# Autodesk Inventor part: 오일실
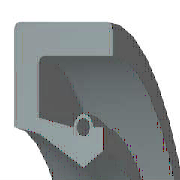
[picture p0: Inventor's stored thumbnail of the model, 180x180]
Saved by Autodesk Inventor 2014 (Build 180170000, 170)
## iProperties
IsCustomPart: 0
Created: 2009-02
Part Number: 오일실
Material: 고무
Description: 오일-실
Document SubType Name: Modeling
Standard: KS B 2804
Designer: 한국산업디자인학원 [http://gmhk.co.kr]
Standards Organization: KS
Language: ko-KR
Size Designation: S - 17 30 8
Categories: <MemberInstance><Categories><Category DisplayName="샤프트 부품" InternalName="7f7aeb1f-a693-4053-b835-cee3144e0d98" Mnemonic="SHFT"><Category DisplayName="실링" Intern
Density: 0.93 g/cm^3
Appearance: 고무 - 검은색 - 버전 1.1
Mass: 1.6913 g
Surface Area: 28.0102 cm^2
Volume: 1.81861 cm^3
Author: pww
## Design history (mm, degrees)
revolve "본체" stored, may be unused: angle "d17" = 90 deg
revolve "스프링1" stored, may be unused: angle "d18" = 90 deg
body "Solid1"
sketch "스케치1"
  geometry: L1 (0, 15)-(8, 15); L2 (8, 15)-(8, 13.75); L3 (8, 13.75)-(1.75, 13.75); L4 (0, 15)-(0, 10.6); L5 (0, 10.6)-(1.75, 10.25); L6 (1.75, 10.25)-(4.9, 8.5); L7 (4.9, 8.5)-(0, 8.5); L8 (6.3, 9.375)-(6.3, 10.6); L9 (0, 0)-(9.586, 0) reference; L10 (4.9, 8.5)-(6.3, 9.375); L11 (0, 18)-(0, -3) reference; L12 (-1.917, 0)-(11.503, 0) reference; L13 (4.2, 10.6)-(1.75, 11.09); L14 (1.75, 11.09)-(1.75, 13.75); L15 (6.3, 10.6)-(5.6, 10.6); C1 r 0.455 at (4.9, 10.6); A1 r 0.7 centre (4.9, 10.6) between (5.6, 10.6) and (4.2, 10.6)
  constraints: 26 end point, 5 horizontal alignment, 4 perpendicular, 2 centre point, 2 collinear, 2 horizontal, 2 parallel, 2 point on circle, 2 point on line, 2 vertical alignment, 1 coincident
  dimensions: "d0" = 30 diameter of L1 L9 (= SD2); "d1" = 18.75 diameter of L8.start L9 (= ABDM); "d2" = 1.25 distance of L1.end L2.end (computed from SD); "d3" = 0.91 diameter of C1 (= SPDI); "d4" = 1.4 diameter of A1 (= SPDA); "d5" = 17 diameter of L6.end L9 (= NND); "d6" = 20.5 diameter of L5.end L9 (= TKDM); "d7" = 21.2 diameter of L4.end L9 (= HLDM); "d8" = 4.9 distance from line of C1.centre L4 (= SPDST); "d9" = 6.3 distance between parallel lines of L8 L4 (= SDI); "d10" = 8 distance between parallel lines of L2 L4 (= SWDT); "d12" = 1.75 distance between parallel lines of L14 L4 (= SD)
fillet "모깎기1" dims "d11" = 0.3 (= RR)
other parameters: "SD2" = 30 [user parameter; used in 1 equation term], "SWDT" = 8 [user parameter; used in 1 equation term], "RR" = 0.3 [user parameter; used in 1 equation term], "SD" = 1.75 [user parameter; used in 2 equation terms], "NND" = 17 [user parameter; used in 1 equation term], "SPDA" = 1.4 [user parameter; used in 1 equation term], "SPDI" = 0.91 [user parameter; used in 1 equation term], "TKDM" = 20.5 [user parameter; used in 1 equation term], "HLDM" = 21.2 [user parameter; used in 1 equation term], "ABDM" = 18.75 [user parameter; used in 1 equation term], "SDI" = 6.3 [user parameter; used in 1 equation term], "SPDST" = 4.9 [user parameter; used in 1 equation term], "d13" = 0, "d14" = 0, "d15" = 0, "LAB" = 0.35 [user parameter]
